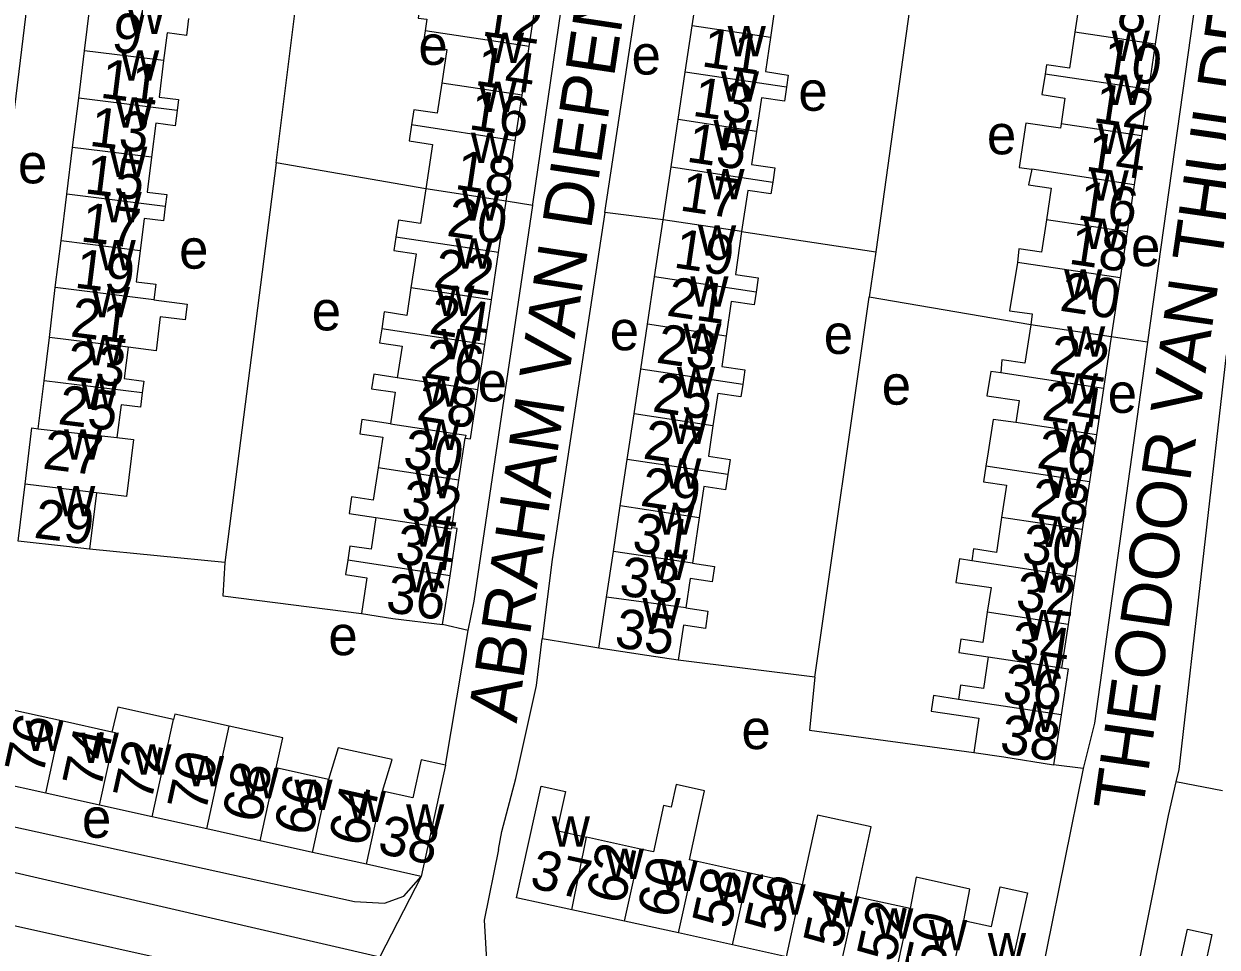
# Model space of a CAD drawing. Extents: x 161775 to 163181, y 382878 to 383925.
# Drawn here: x 162855 to 162975.8, y 383130.9 to 383224.4 of the extents above; entities that cross this region are included whole.
import ezdxf

# ---------------------------------------------------------------- set-up
doc = ezdxf.new("R2010")
doc.units = 0
for name, color, linetype in [('BLT_Basislijn', 7, 'Continuous'), ('BLT_Bebouwing', 7, 'Continuous'), ('BLT_Centroide', 7, 'Continuous'), ('BLT_Huisnummer', 7, 'Continuous'), ('BLT_Huisnummer_ tussenligend', 7, 'Continuous'), ('BLT_Onderverdeling_panden', 7, 'Continuous'), ('BLT_Straatnaam', 7, 'Continuous')]:
    doc.layers.add(name, color=color, linetype=linetype)

msp = doc.modelspace()

# ---------------------------------------------------------------- linework, layer by layer
at = {"layer": 'BLT_Basislijn'}
for p, q in [((162913.79, 383205.27), (162920.4, 383248.77)), ((162947.24, 383244.69), (162941.23, 383201.28)), ((162880.51, 383210.3), (162884.53, 383242.27)), ((162975.49, 383240.34), (162968.75, 383192.16)), ((162880.51, 383210.3), (162875.33, 383169.83)), ((162895.67, 383207.66), (162880.51, 383210.3)), ((162906.5, 383205.99), (162903.81, 383206.44)), ((162919.69, 383204.52), (162913.79, 383205.27)), ((162927.65, 383203.34), (162941.23, 383201.28)), ((162941.23, 383201.28), (162940.57, 383196.69)), ((162935.05, 383158.24), (162940.57, 383196.69)), ((162956.92, 383193.91), (162940.57, 383196.69)), ((162968.75, 383192.16), (162965.08, 383192.68)), ((162875.33, 383169.83), (162861.63, 383171.17)), ((162899.97, 383162.95), (162897.37, 383163.55)), ((162897.66, 383149.32), (162899.97, 383162.95)), ((162913.2, 383161.15), (162907.45, 383162.09)), ((162935.05, 383158.24), (162921.23, 383159.96)), ((162962.22, 383148.97), (162959.24, 383149.36)), ((162784.93, 383148.36), (162891.25, 383124.81)), ((162976.35, 383146.71), (162971.62, 383147.62)), ((162845.8, 383140.33), (162891.01, 383129.91)), ((162895.21, 383138.05), (162891.01, 383129.91))]:
    msp.add_line(p, q, dxfattribs=at)
for points in [[(162906.5, 383205.99), (162906.52, 383206.12), (162912.52, 383247.44), (162912.71, 383249.77)], [(162857.59, 383245.49), (162853.35, 383210.37), (162852.65, 383200.3), (162849.19, 383172.97), (162849.18, 383172.77)], [(162899.97, 383162.95), (162900.56, 383165.93), (162906.5, 383205.99)], [(162913.79, 383205.27), (162908.45, 383170.15), (162907.45, 383162.09)], [(162968.75, 383192.16), (162963.36, 383153.55), (162962.22, 383148.97)], [(162976.71, 383190.88), (162971.92, 383148.89), (162971.62, 383147.62)], [(162875.33, 383169.83), (162875.1, 383166.46), (162889.15, 383164.66)], [(162903.02, 383140.76), (162903.37, 383142.59), (162904.8, 383147.95), (162906.87, 383157.37), (162907.45, 383162.09)], [(162935.05, 383158.24), (162934.53, 383152.87), (162951.16, 383150.6)], [(162962.22, 383148.97), (162956.65, 383121.44), (162953.4, 383116.15)], [(162971.62, 383147.62), (162970.82, 383144.21), (162965.86, 383119.35), (162966.09, 383119.14)], [(162845.21, 383145), (162888.44, 383135.52), (162891.49, 383135.34), (162893.44, 383136.06), (162895.21, 383138.05)], [(162903.02, 383140.76), (162901.57, 383133.6), (162901.86, 383129), (162904.33, 383126.8)]]:
    msp.add_lwpolyline(points, dxfattribs=at)
at = {"layer": 'BLT_Bebouwing'}
for p, q in [((162922.64, 383224.19), (162923.38, 383229.13)), ((162861.12, 383221.66), (162861.66, 383226.04)), ((162906.15, 383222.1), (162906.82, 383226.56)), ((162970.14, 383226.4), (162969.52, 383222.31)), ((162921.93, 383219.49), (162922.64, 383224.19)), ((162905.41, 383217.15), (162906.15, 383222.1)), ((162969.52, 383222.31), (162968.84, 383217.73)), ((162860.52, 383216.86), (162861.12, 383221.66)), ((162921.21, 383214.68), (162921.93, 383219.49)), ((162968.84, 383217.73), (162968.13, 383213.03)), ((162859.9, 383211.86), (162860.52, 383216.86)), ((162904.72, 383212.55), (162905.41, 383217.15)), ((162920.5, 383209.9), (162921.21, 383214.68)), ((162903.81, 383206.44), (162904.72, 383212.55)), ((162968.13, 383213.03), (162967.39, 383208.09)), ((162859.32, 383207.13), (162859.9, 383211.86)), ((162919.69, 383204.52), (162920.5, 383209.9)), ((162967.39, 383208.09), (162966.67, 383203.31)), ((162858.73, 383202.4), (162859.32, 383207.13)), ((162903.02, 383201.22), (162903.81, 383206.44)), ((162918.83, 383198.75), (162919.69, 383204.52)), ((162966.67, 383203.31), (162965.97, 383198.65)), ((162858.15, 383197.68), (162858.73, 383202.4)), ((162902.31, 383196.43), (162903.02, 383201.22)), ((162918.11, 383193.96), (162918.83, 383198.75)), ((162965.97, 383198.65), (162965.08, 383192.68)), ((162857.56, 383192.62), (162858.15, 383197.68)), ((162901.63, 383191.92), (162902.31, 383196.43)), ((162917.43, 383189.42), (162918.11, 383193.96)), ((162857.03, 383188.24), (162857.56, 383192.62)), ((162900.95, 383187.32), (162901.63, 383191.92)), ((162856.43, 383183.38), (162857.03, 383188.24)), ((162916.76, 383184.89), (162917.43, 383189.42)), ((162964.29, 383187.47), (162963.59, 383182.77)), ((162916.06, 383180.25), (162916.76, 383184.89)), ((162899.02, 383178.18), (162899.66, 383182.43)), ((162963.59, 383182.77), (162962.87, 383178)), ((162915.36, 383175.56), (162916.06, 383180.25)), ((162854.39, 383172), (162855.09, 383177.78)), ((162898.29, 383173.35), (162899.02, 383178.18)), ((162962.87, 383178), (162962.14, 383173.16)), ((162862.34, 383176.88), (162861.63, 383171.17)), ((162914.67, 383170.95), (162915.36, 383175.56)), ((162962.14, 383173.16), (162961.43, 383168.43)), ((162913.98, 383166.34), (162914.67, 383170.95)), ((162897.37, 383163.55), (162898.12, 383168.5)), ((162961.43, 383168.43), (162960.71, 383163.57)), ((162913.2, 383161.15), (162913.98, 383166.34)), ((162960.71, 383163.57), (162960.04, 383159.17)), ((162858.78, 383153.79), (162853.06, 383155.04)), ((162960, 383154.4), (162959.24, 383149.36)), ((162863.88, 383152.67), (162858.78, 383153.79)), ((162885.83, 383147.87), (162880.52, 383149.03)), ((162897.66, 383149.32), (162895.21, 383138.05)), ((162857.18, 383146.47), (162851.46, 383147.73)), ((162862.64, 383145.26), (162857.18, 383146.47)), ((162867.97, 383144.08), (162862.64, 383145.26)), ((162873.49, 383142.86), (162867.97, 383144.08)), ((162878.88, 383141.66), (162873.49, 383142.86)), ((162884.21, 383140.48), (162878.88, 383141.66)), ((162917.41, 383140.81), (162911.95, 383142.01)), ((162889.67, 383139.28), (162884.21, 383140.48)), ((162895.21, 383138.05), (162889.67, 383139.28)), ((162933.78, 383137.2), (162928.33, 383138.4)), ((162944.7, 383134.79), (162939.24, 383135.99)), ((162915.8, 383133.52), (162910.44, 383134.65)), ((162921.26, 383132.32), (162915.8, 383133.52)), ((162926.72, 383131.12), (162921.26, 383132.32)), ((162932.18, 383129.91), (162926.72, 383131.12))]:
    msp.add_line(p, q, dxfattribs=at)
for points in [[(162898.7, 383227.78), (162895.41, 383228.28), (162894.91, 383224.97), (162895.78, 383224.84), (162895.61, 383223.69)], [(162960.33, 383228.05), (162959.62, 383228.15), (162959.41, 383226.78), (162961.82, 383226.42), (162961.38, 383223.53)], [(162933.76, 383227.57), (162933.52, 383225.94), (162931.05, 383226.31), (162930.56, 383223.01)], [(162871.65, 383224.91), (162871.43, 383223.21), (162869.47, 383223.46), (162869.12, 383220.67)], [(162895.61, 383223.69), (162895.38, 383222.15), (162897.8, 383221.79), (162897.28, 383218.37)], [(162961.38, 383223.53), (162960.83, 383219.88), (162958.52, 383220.23), (162958.38, 383219.3)], [(162930.56, 383223.01), (162930.05, 383219.55), (162932.37, 383219.2), (162932.19, 383217.96)], [(162869.12, 383220.67), (162868.67, 383216.97), (162870.63, 383216.73), (162870.49, 383215.62)], [(162958.38, 383219.3), (162958.06, 383217.22), (162960.38, 383216.87), (162959.99, 383214.26)], [(162897.28, 383218.37), (162896.82, 383215.33), (162894.45, 383215.69), (162894.22, 383214.14)], [(162932.19, 383217.96), (162931.98, 383216.55), (162929.66, 383216.89), (162929.15, 383213.49)], [(162870.49, 383215.62), (162870.3, 383214.07), (162868.34, 383214.31), (162867.91, 383210.87)], [(162894.22, 383214.14), (162893.97, 383212.52), (162896.35, 383212.16), (162895.67, 383207.66)], [(162959.99, 383214.26), (162959.92, 383213.82), (162956.43, 383214.34), (162955.75, 383209.84), (162957.02, 383209.65)], [(162929.15, 383213.49), (162928.65, 383210.14), (162931.01, 383209.79), (162930.79, 383208.36)], [(162867.91, 383210.87), (162867.47, 383207.34), (162869.44, 383207.09), (162869.29, 383205.9)], [(162957.02, 383209.65), (162956.68, 383208.08), (162959, 383207.73), (162958.52, 383204.54)], [(162895.67, 383207.66), (162895.14, 383204.17), (162892.9, 383204.51), (162892.64, 383202.78)], [(162930.79, 383208.36), (162930.62, 383207.16), (162928.27, 383207.51), (162927.65, 383203.34)], [(162869.29, 383205.9), (162869.11, 383204.43), (162867.15, 383204.68), (162866.74, 383201.41)], [(162958.52, 383204.54), (162958.02, 383201.25), (162955.71, 383201.6), (162955.59, 383200.21)], [(162892.64, 383202.78), (162892.43, 383201.43), (162894.68, 383201.1), (162894.16, 383197.66)], [(162927.65, 383203.34), (162927.01, 383198.99), (162929.32, 383198.65), (162929.11, 383197.21)], [(162866.74, 383201.41), (162866.35, 383198.27), (162868.32, 383198.03), (162868.12, 383196.42)], [(162955.59, 383200.21), (162954.76, 383195.32), (162957.08, 383195)], [(162894.16, 383197.66), (162893.74, 383194.86), (162891.46, 383195.21), (162891.2, 383193.49)], [(162929.11, 383197.21), (162928.92, 383195.92), (162926.6, 383196.26), (162926.09, 383192.76)], [(162868.12, 383196.42), (162871.49, 383196), (162871.29, 383194.4), (162868.77, 383194.72), (162868.35, 383191.28), (162865.53, 383191.63)], [(162957.08, 383195), (162956.92, 383193.91)], [(162891.2, 383193.49), (162890.99, 383192.09), (162893.27, 383191.74), (162892.78, 383188.55)], [(162956.92, 383193.91), (162956.33, 383190.02), (162954.01, 383190.37), (162953.9, 383189.04)], [(162926.09, 383192.76), (162925.63, 383189.68), (162927.98, 383189.33), (162927.76, 383187.87)], [(162965.08, 383192.68), (162964.29, 383187.47)], [(162865.53, 383191.63), (162865.14, 383188.46), (162867.11, 383188.21), (162866.96, 383187.01)], [(162892.78, 383188.55), (162890.4, 383188.91), (162890.18, 383187.43), (162892.56, 383187.07), (162892.08, 383183.88)], [(162953.9, 383189.04), (162952.87, 383189.19), (162952.49, 383186.72), (162955.76, 383186.23), (162955.42, 383184)], [(162899.66, 383182.43), (162900.21, 383182.35), (162900.95, 383187.32)], [(162927.76, 383187.87), (162927.57, 383186.6), (162925.23, 383186.94), (162924.74, 383183.69)], [(162866.96, 383187.01), (162866.78, 383185.55), (162864.81, 383185.79), (162864.4, 383182.5)], [(162855.09, 383177.78), (162855.78, 383183.46), (162856.43, 383183.38)], [(162892.08, 383183.88), (162889.2, 383184.31), (162888.98, 383182.88), (162891.32, 383182.52), (162890.85, 383179.41)], [(162924.74, 383183.69), (162924.29, 383180.61), (162926.49, 383180.28), (162926.26, 383178.73)], [(162955.42, 383184), (162953.1, 383184.33), (162952.6, 383181.03), (162952.39, 383179.58)], [(162864.4, 383182.5), (162866.07, 383182.3), (162865.35, 383176.51), (162862.34, 383176.88)], [(162890.85, 383179.41), (162890.35, 383176.14), (162888.15, 383176.48), (162887.9, 383174.81), (162890.62, 383174.4)], [(162926.26, 383178.73), (162926.03, 383177.21), (162923.83, 383177.54), (162923.36, 383174.37)], [(162952.39, 383179.58), (162952.15, 383178.02), (162954.46, 383177.67), (162953.97, 383174.39)], [(162890.62, 383174.4), (162890.14, 383171.17), (162887.98, 383171.5), (162887.77, 383170.06)], [(162923.36, 383174.37), (162922.68, 383169.77)], [(162953.97, 383174.39), (162953.44, 383170.86), (162951.12, 383171.21), (162950.94, 383170.01)], [(162898.12, 383168.5), (162898.83, 383173.27), (162898.29, 383173.35)], [(162861.63, 383171.17), (162859.27, 383171.46), (162854.39, 383172)], [(162950.94, 383170.01), (162949.7, 383170.2), (162949.34, 383167.82), (162952.9, 383167.29), (162952.52, 383164.8)], [(162887.77, 383170.06), (162887.55, 383168.61), (162889.7, 383168.28), (162889.15, 383164.66)], [(162922.68, 383169.77), (162924.9, 383169.44), (162924.66, 383167.88), (162922.45, 383168.21), (162922.01, 383165.23)], [(162889.15, 383164.66), (162892.32, 383164.18), (162897.37, 383163.55)], [(162922.01, 383165.23), (162924.24, 383164.91), (162923.98, 383163.16), (162921.76, 383163.49), (162921.23, 383159.96)], [(162952.52, 383164.8), (162952.06, 383161.74), (162949.83, 383162.07), (162949.63, 383160.72), (162952.62, 383160.27)], [(162921.23, 383159.96), (162918.05, 383160.43), (162913.2, 383161.15)], [(162952.62, 383160.27), (162952.14, 383157.07), (162949.82, 383157.42), (162949.6, 383155.97)], [(162960.04, 383159.17), (162960.7, 383159.07), (162960, 383154.4)], [(162949.6, 383155.97), (162947.09, 383156.35), (162946.85, 383154.79), (162949.36, 383154.41), (162951.68, 383154.06), (162951.16, 383150.6)], [(162870.13, 383153.95), (162864.48, 383155.18), (162863.88, 383152.67)], [(162875.77, 383153.27), (162870.25, 383154.48), (162870.13, 383153.95)], [(162880.52, 383149.03), (162881.19, 383152.09), (162875.77, 383153.27)], [(162891.29, 383146.67), (162892.27, 383149.87), (162886.78, 383151.08), (162885.83, 383147.87)], [(162897.66, 383149.32), (162895.21, 383149.86), (162894.37, 383146), (162891.29, 383146.67)], [(162951.16, 383150.6), (162954.2, 383150.15), (162959.24, 383149.36)], [(162910.44, 383134.65), (162904.85, 383135.87), (162907.34, 383147.17), (162909.8, 383146.63), (162908.93, 383142.68), (162911.95, 383142.01)], [(162922.87, 383139.61), (162922.37, 383139.72), (162923.39, 383144.42), (162923.9, 383146.72), (162921.03, 383147.35), (162920.52, 383145.05), (162919.75, 383145.22), (162918.71, 383140.52), (162917.41, 383140.81)], [(162939.24, 383135.99), (162940.75, 383143.07), (162935.32, 383144.26), (162933.78, 383137.2)], [(162928.33, 383138.4), (162922.87, 383139.61)], [(162950.16, 383133.59), (162950.74, 383136.77), (162945.31, 383137.96), (162944.7, 383134.79)], [(162950.16, 383133.59), (162952.96, 383132.97), (162953.84, 383136.98), (162956.6, 383136.37), (162954.11, 383125.08), (162948.56, 383126.3)], [(162975.6, 383120.33), (162970.32, 383121.52), (162972.79, 383132.71), (162975.27, 383132.17), (162974.42, 383128.31), (162977.23, 383127.68)]]:
    msp.add_lwpolyline(points, dxfattribs=at)
at = {"layer": 'BLT_Onderverdeling_panden'}
for p, q in [((162906.15, 383222.1), (162895.61, 383223.69)), ((162869.12, 383220.67), (162861.12, 383221.66)), ((162932.19, 383217.96), (162921.93, 383219.49)), ((162968.84, 383217.73), (162958.38, 383219.3)), ((162905.41, 383217.15), (162897.28, 383218.37)), ((162870.49, 383215.62), (162860.52, 383216.86)), ((162904.72, 383212.55), (162894.22, 383214.14)), ((162968.13, 383213.03), (162959.99, 383214.26)), ((162867.91, 383210.87), (162859.9, 383211.86)), ((162920.5, 383209.9), (162930.79, 383208.36)), ((162967.39, 383208.09), (162957.02, 383209.65)), ((162903.81, 383206.44), (162895.67, 383207.66)), ((162869.29, 383205.9), (162859.32, 383207.13)), ((162966.67, 383203.31), (162958.52, 383204.54)), ((162903.02, 383201.22), (162892.64, 383202.78)), ((162866.74, 383201.41), (162858.73, 383202.4)), ((162929.11, 383197.21), (162918.83, 383198.75)), ((162868.12, 383196.42), (162858.15, 383197.68)), ((162902.31, 383196.43), (162894.16, 383197.66)), ((162901.63, 383191.92), (162891.2, 383193.49)), ((162926.09, 383192.76), (162918.11, 383193.96)), ((162865.53, 383191.63), (162857.56, 383192.62)), ((162866.96, 383187.01), (162857.03, 383188.24)), ((162900.95, 383187.32), (162892.78, 383188.55)), ((162927.76, 383187.87), (162917.43, 383189.42)), ((162964.29, 383187.47), (162953.9, 383189.04)), ((162924.74, 383183.69), (162916.76, 383184.89)), ((162963.59, 383182.77), (162955.42, 383184)), ((162856.43, 383183.38), (162864.4, 383182.5)), ((162926.26, 383178.73), (162916.06, 383180.25)), ((162899.02, 383178.18), (162890.85, 383179.41)), ((162962.87, 383178), (162952.39, 383179.58)), ((162862.34, 383176.88), (162855.09, 383177.78)), ((162923.36, 383174.37), (162915.36, 383175.56)), ((162962.14, 383173.16), (162953.97, 383174.39)), ((162922.68, 383169.77), (162914.67, 383170.95)), ((162898.12, 383168.5), (162887.77, 383170.06)), ((162961.43, 383168.43), (162950.94, 383170.01)), ((162922.01, 383165.23), (162913.98, 383166.34)), ((162960.71, 383163.57), (162952.52, 383164.8)), ((162952.62, 383160.27), (162960.04, 383159.17)), ((162960, 383154.4), (162949.6, 383155.97)), ((162857.18, 383146.47), (162858.78, 383153.79)), ((162867.97, 383144.08), (162870.13, 383153.95)), ((162873.49, 383142.86), (162875.77, 383153.27)), ((162878.88, 383141.66), (162880.52, 383149.03)), ((162884.21, 383140.48), (162885.83, 383147.87)), ((162889.67, 383139.28), (162891.29, 383146.67)), ((162910.44, 383134.65), (162911.95, 383142.01)), ((162915.8, 383133.52), (162917.41, 383140.81)), ((162921.26, 383132.32), (162922.87, 383139.61)), ((162926.72, 383131.12), (162928.33, 383138.4)), ((162932.18, 383129.91), (162933.78, 383137.2)), ((162937.64, 383128.71), (162939.24, 383135.99)), ((162943.1, 383127.51), (162944.7, 383134.79)), ((162948.56, 383126.3), (162950.16, 383133.59))]:
    msp.add_line(p, q, dxfattribs=at)
for points in [[(162930.56, 383223.01), (162922.64, 383224.19)], [(162969.52, 383222.31), (162961.38, 383223.53)], [(162929.15, 383213.49), (162921.21, 383214.68)], [(162927.65, 383203.34), (162919.69, 383204.52)], [(162965.97, 383198.65), (162955.59, 383200.21)], [(162965.08, 383192.68), (162956.92, 383193.91)], [(162892.08, 383183.88), (162899.72, 383182.72), (162899.66, 383182.43)], [(162890.62, 383174.4), (162898.27, 383173.25), (162898.29, 383173.35)], [(162862.64, 383145.26), (162864.25, 383152.59), (162863.88, 383152.67)]]:
    msp.add_lwpolyline(points, dxfattribs=at)

# ---------------------------------------------------------------- texts
at = {"layer": 'BLT_Centroide'}
for s, p in [('w', (162865.39, 383223.34)), ('e', (162894.92, 383220.23)), ('w', (162901.75, 383220.41)), ('w', (162926.23, 383221.09)), ('w', (162965.11, 383220.62)), ('e', (162916.5, 383219.25)), ('w', (162864.8, 383218.62)), ('w', (162901, 383215.47)), ('w', (162925.54, 383216.5)), ('e', (162933.39, 383215.58)), ('w', (162964.43, 383216.16)), ('w', (162864.22, 383213.88)), ('w', (162924.8, 383211.56)), ('e', (162952.48, 383211.17)), ('w', (162963.69, 383211.19)), ('w', (162900.23, 383210.28)), ('e', (162854.37, 383208.23)), ('w', (162863.6, 383208.88)), ('w', (162924.08, 383206.62)), ('w', (162962.98, 383206.47)), ('w', (162863.03, 383204.28)), ('w', (162899.35, 383204.44)), ('w', (162923.23, 383200.91)), ('w', (162962.25, 383201.59)), ('e', (162967.07, 383199.84)), ('w', (162862.43, 383199.41)), ('e', (162870.69, 383199.59)), ('w', (162898.62, 383199.59)), ('w', (162960.3, 383196.44)), ('w', (162922.45, 383195.75)), ('w', (162861.84, 383194.66)), ('w', (162896.73, 383194.78)), ('e', (162884.12, 383193.34)), ('e', (162914.29, 383191.33)), ('w', (162897.23, 383190.41)), ('w', (162921.73, 383190.94)), ('e', (162935.96, 383190.96)), ('w', (162960.6, 383190.69)), ('w', (162861.24, 383189.81)), ('w', (162921.09, 383186.56)), ('w', (162860.69, 383185.38)), ('w', (162895.3, 383185.62)), ('e', (162900.92, 383186.14)), ('e', (162941.83, 383185.82)), ('w', (162959.88, 383185.91)), ('e', (162964.71, 383184.99)), ('w', (162920.38, 383181.84)), ('w', (162895.3, 383181.22)), ('w', (162959.15, 383181)), ('w', (162859.03, 383180.25)), ('w', (162919.71, 383177.31)), ('w', (162894.55, 383176.34)), ('w', (162958.45, 383176.38)), ('w', (162858.33, 383174.5)), ('w', (162919.02, 383172.66)), ('w', (162894.37, 383171.44)), ('w', (162957.7, 383171.41)), ('w', (162918.34, 383168.06)), ('w', (162893.67, 383166.81)), ('w', (162957.01, 383166.78)), ('w', (162917.6, 383163.16)), ('w', (162956.28, 383161.97)), ('e', (162885.8, 383160.45)), ('w', (162956.3, 383157.34)), ('w', (162955.6, 383152.66)), ('w', (162855.12, 383150.75)), ('e', (162927.63, 383150.94)), ('w', (162860.72, 383149.53)), ('w', (162866.05, 383148.34)), ('w', (162871.38, 383147.17)), ('w', (162876.91, 383145.95)), ('w', (162882.36, 383144.77)), ('w', (162887.75, 383143.56)), ('e', (162860.85, 383141.96)), ('w', (162893.67, 383142.28)), ('w', (162908.42, 383141.05)), ('w', (162913.88, 383137.77)), ('w', (162919.33, 383136.56)), ('w', (162924.8, 383135.36)), ('w', (162930.25, 383134.16)), ('w', (162935.72, 383132.95)), ('w', (162941.17, 383131.75)), ('w', (162946.62, 383130.55)), ('w', (162952.58, 383129.23))]:
    msp.add_text(s, height=4, dxfattribs=at).set_placement(p)
at = {"layer": 'BLT_Huisnummer'}
for s, rotation, p in [('12', 351.4567, (162901.25, 383223.21)), ('11', 351.5814, (162923.48, 383220.1)), ('10', 351.4759, (162963.96, 383219.01)), ('11', 352.9392, (162862.6, 383216.91)), ('16', 351.4518, (162899.91, 383213.73)), ('15', 351.5853, (162921.96, 383210.44)), ('14', 351.4765, (162962.37, 383209.52)), ('15', 352.9383, (162861.03, 383207.23)), ('20', 351.456, (162897.68, 383202.93)), ('17', 352.9357, (162860.6, 383202.37)), ('19', 351.5822, (162920.66, 383199.72)), ('18', 351.4762, (162960.66, 383200.11)), ('24', 351.4543, (162895.9, 383193.04)), ('21', 352.9401, (162859.58, 383192.74)), ('23', 351.5812, (162918.89, 383190.09)), ('22', 351.4796, (162958.65, 383188.97)), ('25', 352.9384, (162858.32, 383183.87)), ('28', 351.4515, (162894.63, 383184.29)), ('27', 351.5861, (162917.56, 383180.38)), ('26', 351.4751, (162957.42, 383179.43)), ('32', 351.4184, (162893.07, 383174.31)), ('29', 352.9361, (162855.89, 383172.35)), ('31', 351.585, (162916.45, 383170.96)), ('30', 354.0064, (162955.95, 383169.78)), ('36', 351.4194, (162891.5, 383164.86)), ('35', 351.5854, (162914.67, 383161.29)), ('34', 351.4233, (162954.68, 383160.01)), ('38', 351.4194, (162953.67, 383150.56)), ('76', 77.6583, (162856.88, 383148.15)), ('72', 77.6567, (162867.85, 383145.49)), ('68', 77.655, (162878.89, 383143.32)), ('64', 77.6517, (162889.68, 383140.93)), ('38', 347.6542, (162890.66, 383140.44)), ('62', 77.5737, (162915.75, 383135.08)), ('37', 347.5711, (162906.07, 383136.94)), ('58', 77.572, (162926.48, 383132.61)), ('54', 77.572, (162937.73, 383130.59)), ('50', 77.572, (162948.02, 383128.11))]:
    msp.add_text(s, height=4, rotation=rotation, dxfattribs=at).set_placement(p)
at = {"layer": 'BLT_Huisnummer_ tussenligend'}
for s, rotation, p in [('8', 351.4761, (162965.49, 383223.77)), ('9', 352.9392, (162863.75, 383221.61)), ('14', 351.4518, (162900.55, 383218.21)), ('13', 351.5853, (162922.56, 383215.09)), ('12', 351.4759, (162963.14, 383214.44)), ('13', 352.9383, (162861.5, 383212.05)), ('18', 351.456, (162898.5, 383207.68)), ('17', 351.5822, (162921.27, 383205.5)), ('16', 351.4765, (162961.54, 383204.6)), ('22', 351.4543, (162896.34, 383197.73)), ('19', 352.9357, (162860.01, 383197.68)), ('20', 351.4762, (162959.75, 383195.35)), ('21', 351.5812, (162919.94, 383194.85)), ('23', 352.9401, (162859.13, 383188.32)), ('26', 351.4515, (162895.35, 383188.6)), ('25', 351.5861, (162918.51, 383185.15)), ('24', 351.4796, (162957.93, 383184.3)), ('27', 352.9384, (162856.78, 383179.36)), ('30', 351.4184, (162893.25, 383179.44)), ('29', 351.585, (162917.28, 383175.6)), ('28', 351.4751, (162956.73, 383174.48)), ('34', 351.4184, (162892.46, 383169.82)), ('33', 351.585, (162915.15, 383166.55)), ('32', 354.0064, (162955.32, 383164.97)), ('36', 351.4233, (162953.95, 383155.7)), ('74', 77.6567, (162862.73, 383146.75)), ('70', 77.655, (162873.35, 383144.38)), ('66', 77.6517, (162884.14, 383141.99)), ('60', 77.572, (162920.93, 383133.67)), ('56', 77.572, (162931.77, 383132.08)), ('52', 77.572, (162943.15, 383129.24))]:
    msp.add_text(s, height=4, rotation=rotation, dxfattribs=at).set_placement(p)
at = {"layer": 'BLT_Straatnaam'}
for s, rotation, p in [('ABRAHAM VAN DIEPENBEECKSTRAAT', 81.4307, (162904.86, 383153.49)), ('JAN VAN GOYENSTRAAT', 82.9955, (162847.96, 383186.04)), ('THEODOOR VAN THULDENSTRAAT', 81.8335, (162968.23, 383144.45))]:
    msp.add_text(s, height=5, rotation=rotation, dxfattribs=at).set_placement(p)

doc.saveas('drawing.dxf')
